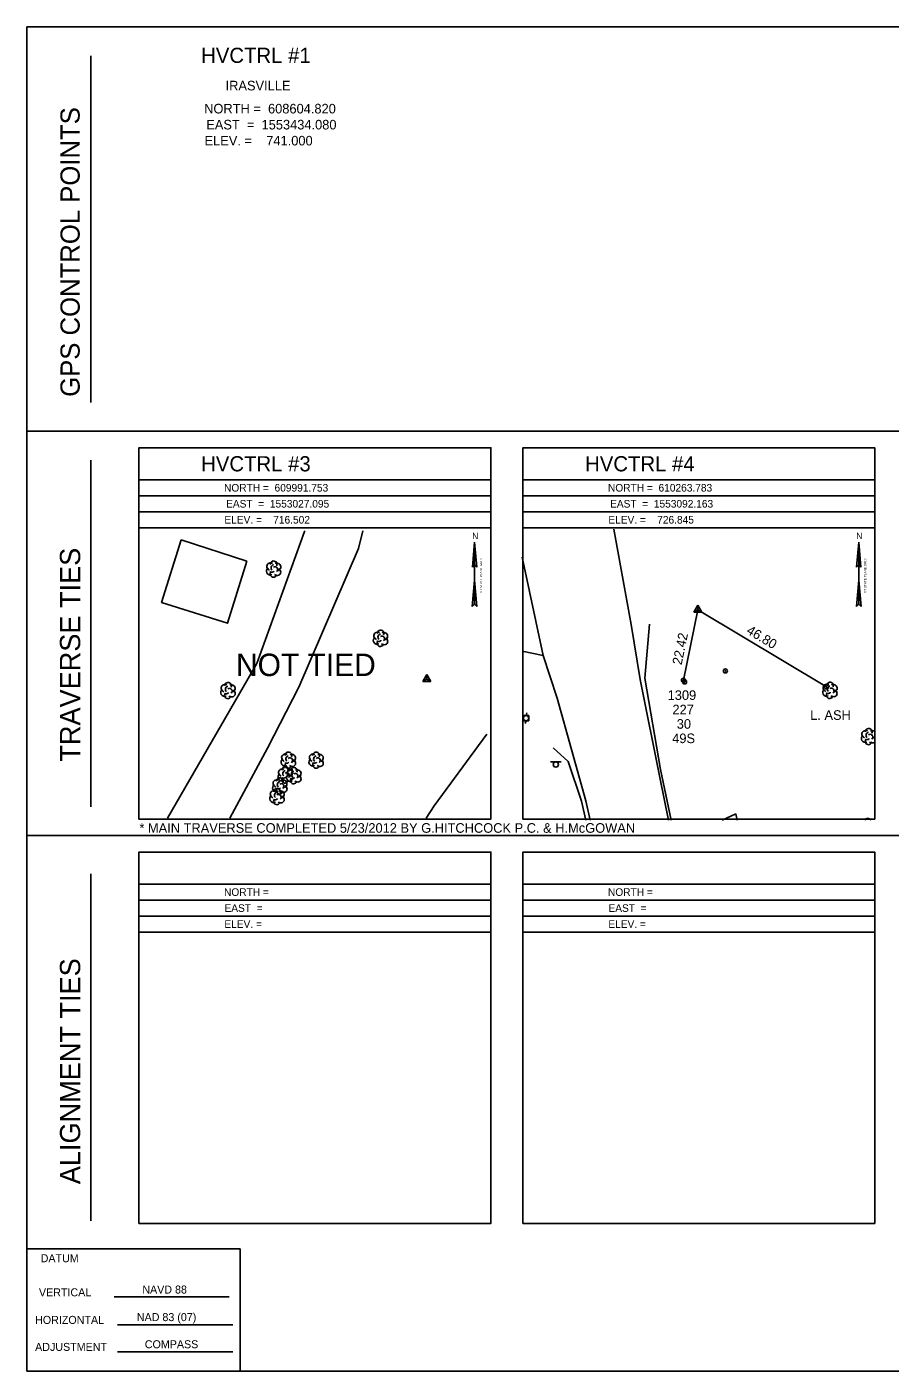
# Model space of a CAD drawing. Extents: x 1553683 to 1554323, y 609712 to 610132.
# Drawn here: x 1553683 to 1553952.8, y 609712.3 to 610132.3 of the extents above; entities that cross this region are included whole.
import ezdxf

# ---------------------------------------------------------------- set-up
doc = ezdxf.new("R2010")
doc.units = 0
for name, color, linetype in [('CBP', 7, 'Continuous'), ('CPSM', 7, 'Continuous'), ('Default', 7, 'Continuous'), ('L_C', 7, 'Continuous'), ('LAWA', 7, 'Continuous'), ('LAWE', 7, 'Continuous'), ('LBC', 7, 'Continuous'), ('LTD', 7, 'Continuous'), ('NBL1', 7, 'Continuous'), ('NBL2', 7, 'Continuous'), ('NNA_P', 7, 'Continuous'), ('PET', 7, 'Continuous'), ('PEU', 7, 'Continuous'), ('RGR', 7, 'Continuous'), ('SSGN', 7, 'Continuous'), ('U_C', 7, 'Continuous'), ('UP', 7, 'Continuous'), ('UPGW', 7, 'Continuous')]:
    doc.layers.add(name, color=color, linetype=linetype)

msp = doc.modelspace()

# ---------------------------------------------------------------- linework, layer by layer
at = {"layer": 'CBP'}
for centre, radius in [((1553888.16, 609928.2), 0.625), ((1553888.16, 609928.2), 0.0833), ((1553932.86, 609926.09), 0.625), ((1553932.86, 609926.09), 0.0833)]:
    msp.add_circle(centre, radius, dxfattribs=at)
at = {"layer": 'CPSM'}
for p, q in [((1553891.46, 609949.43), (1553892.71, 609951.6)), ((1553891.46, 609949.43), (1553892.71, 609950.15)), ((1553891.46, 609949.43), (1553893.96, 609949.43)), ((1553893.96, 609949.43), (1553892.71, 609951.6)), ((1553892.71, 609950.15), (1553892.71, 609951.6)), ((1553892.71, 609950.15), (1553892.71, 609950.15)), ((1553892.71, 609950.15), (1553893.96, 609949.43)), ((1553806.69, 609927.77), (1553807.94, 609929.94)), ((1553806.69, 609927.77), (1553807.94, 609928.49)), ((1553809.19, 609927.77), (1553807.94, 609929.94)), ((1553807.94, 609928.49), (1553807.94, 609929.94)), ((1553807.94, 609928.49), (1553807.94, 609928.49)), ((1553807.94, 609928.49), (1553809.19, 609927.77)), ((1553806.69, 609927.77), (1553809.19, 609927.77))]:
    msp.add_line(p, q, dxfattribs=at)
at = {"layer": 'Default'}
for p, q in [((1553888.16, 609928.2), (1553892.71, 609950.15)), ((1553892.71, 609950.15), (1553932.86, 609926.09))]:
    msp.add_line(p, q, dxfattribs=at)
at = {"layer": 'LAWA'}
for points in [[(1553904.54, 609886.5), (1553900.28, 609884.47)], [(1553904.54, 609886.5), (1553904.91, 609884.47)]]:
    msp.add_lwpolyline(points, dxfattribs=at)
at = {"layer": 'LAWE'}
msp.add_lwpolyline([(1553826.71, 609911.3), (1553810.31, 609889), (1553807.72, 609885.14)], dxfattribs=at)
at = {"layer": 'LBC'}
for points in [[(1553751.67, 609965.42), (1553745.63, 609946.01), (1553725.09, 609952.48), (1553731.24, 609972.07)], [(1553751.67, 609965.42), (1553731.24, 609972.07)]]:
    msp.add_lwpolyline(points, dxfattribs=at)
at = {"layer": 'LTD'}
for p, q in [((1553760.04, 609962.97), (1553760.04, 609962.97)), ((1553760.04, 609962.97), (1553760.04, 609962.97)), ((1553793.47, 609941.33), (1553793.47, 609941.33)), ((1553793.47, 609941.33), (1553793.47, 609941.33)), ((1553745.8, 609925), (1553745.8, 609925)), ((1553745.8, 609925), (1553745.8, 609925)), ((1553933.91, 609925.08), (1553933.91, 609925.08)), ((1553933.91, 609925.08), (1553933.91, 609925.08)), ((1553946.03, 609910.64), (1553946.03, 609910.64)), ((1553946.03, 609910.64), (1553946.03, 609910.64)), ((1553764.68, 609903.26), (1553764.68, 609903.26)), ((1553764.68, 609903.26), (1553764.68, 609903.26)), ((1553773.35, 609903.28), (1553773.35, 609903.28)), ((1553773.35, 609903.28), (1553773.35, 609903.28)), ((1553762, 609895.23), (1553762, 609895.23)), ((1553762, 609895.23), (1553762, 609895.23)), ((1553763.73, 609898.64), (1553763.73, 609898.64)), ((1553763.73, 609898.64), (1553763.73, 609898.64)), ((1553766.38, 609898.43), (1553766.38, 609898.43)), ((1553766.38, 609898.43), (1553766.38, 609898.43)), ((1553761.13, 609891.88), (1553761.13, 609891.88)), ((1553761.13, 609891.88), (1553761.13, 609891.88))]:
    msp.add_line(p, q, dxfattribs=at)
for centre, start, end in [((1553760.09, 609964.41), 335.5272, 180.9563), ((1553793.52, 609942.77), 335.5272, 180.9563), ((1553745.84, 609926.44), 335.5272, 180.9563), ((1553933.96, 609926.52), 335.5272, 180.9563), ((1553946.07, 609912.07), 335.5272, 180.9563), ((1553764.73, 609904.7), 335.5272, 180.9563), ((1553773.4, 609904.71), 335.5272, 180.9563), ((1553763.78, 609900.07), 335.5272, 180.9563), ((1553766.43, 609899.87), 335.5272, 180.9563), ((1553762.05, 609896.66), 335.5272, 180.9563), ((1553761.18, 609893.31), 335.5272, 180.9563), ((1553945.76, 609883.98), 27.7565, 152.2435)]:
    msp.add_arc(centre, 1.05, start, end, dxfattribs=at)
for centre, major_axis, ratio, start_param, end_param in [((1553758.96, 609962.26), (0.58, -1.04), 0.959034, 3.141593, 6.283185), ((1553759.25, 609963.64), (1.21, -0.51), 0.895232, 1.570796, 4.712389), ((1553759.58, 609962.22), (-0.625, -0.083), 0.423636, 0, 3.141593), ((1553759.83, 609963.43), (-0.208, -0.792), 0.645439, 3.141593, 6.283185), ((1553760.54, 609962.81), (-0.5, 0.667), 0.989748, 3.141593, 6.283185), ((1553761.04, 609962.14), (-1.09, 0.79), 0.841452, 1.570796, 4.712389), ((1553761.08, 609963.56), (-1.14, -0.48), 0.949671, 1.570796, 4.712389), ((1553760.04, 609961.47), (0.26, 1.06), 0.942809, 1.570796, 4.712389), ((1553792.39, 609940.62), (0.58, -1.04), 0.959034, 3.141593, 6.283185), ((1553792.68, 609942), (1.21, -0.51), 0.895232, 1.570796, 4.712389), ((1553793.26, 609941.79), (-0.208, -0.792), 0.645439, 3.141593, 6.283185), ((1553793.97, 609941.17), (-0.5, 0.667), 0.989748, 3.141593, 6.283185), ((1553794.47, 609940.5), (-1.09, 0.79), 0.841452, 1.570796, 4.712389), ((1553794.51, 609941.92), (-1.14, -0.48), 0.949671, 1.570796, 4.712389), ((1553793.47, 609939.83), (0.26, 1.06), 0.942809, 1.570796, 4.712389), ((1553793.01, 609940.58), (-0.625, -0.083), 0.423636, 0, 3.141593), ((1553744.71, 609924.3), (0.58, -1.04), 0.959034, 3.141593, 6.283185), ((1553745, 609925.67), (1.21, -0.51), 0.895232, 1.570796, 4.712389), ((1553745.34, 609924.25), (-0.625, -0.083), 0.423636, 0, 3.141593), ((1553745.59, 609925.46), (-0.208, -0.792), 0.645439, 3.141593, 6.283185), ((1553746.3, 609924.84), (-0.5, 0.667), 0.989748, 3.141593, 6.283185), ((1553746.8, 609924.17), (-1.09, 0.79), 0.841452, 1.570796, 4.712389), ((1553746.84, 609925.59), (-1.14, -0.48), 0.949671, 1.570796, 4.712389), ((1553932.83, 609924.38), (0.58, -1.04), 0.959034, 3.141593, 6.283185), ((1553933.12, 609925.75), (1.21, -0.51), 0.895232, 1.570796, 4.712389), ((1553933.45, 609924.33), (-0.625, -0.083), 0.423636, 0, 3.141593), ((1553933.7, 609925.54), (-0.208, -0.792), 0.645439, 3.141593, 6.283185), ((1553934.41, 609924.92), (-0.5, 0.667), 0.989748, 3.141593, 6.283185), ((1553934.91, 609924.25), (-1.09, 0.79), 0.841452, 1.570796, 4.712389), ((1553934.95, 609925.67), (-1.14, -0.48), 0.949671, 1.570796, 4.712389), ((1553745.8, 609923.5), (0.26, 1.06), 0.942809, 1.570796, 4.712389), ((1553933.91, 609923.58), (0.26, 1.06), 0.942809, 1.570796, 4.712389), ((1553945.24, 609911.3), (1.21, -0.51), 0.895232, 1.570796, 4.712389), ((1553945.82, 609911.09), (-0.208, -0.792), 0.645439, 3.141593, 6.283185), ((1553946.53, 609910.47), (-0.5, 0.667), 0.989748, 3.141593, 6.283185), ((1553947.07, 609911.22), (-1.14, -0.48), 0.949671, 3.816929, 4.712389), ((1553944.94, 609909.93), (0.58, -1.04), 0.959034, 3.141593, 6.283185), ((1553946.03, 609909.14), (0.26, 1.06), 0.942809, 1.570796, 4.712389), ((1553945.57, 609909.89), (-0.625, -0.083), 0.423636, 0, 3.141593), ((1553947.03, 609909.8), (-1.09, 0.79), 0.841452, 1.570796, 2.649237), ((1553947.07, 609911.22), (-1.14, -0.48), 0.949671, 1.570796, 1.701834), ((1553763.6, 609902.55), (0.58, -1.04), 0.959034, 3.141593, 6.283185), ((1553763.89, 609903.93), (1.21, -0.51), 0.895232, 1.570796, 4.712389), ((1553764.47, 609903.72), (-0.208, -0.792), 0.645439, 3.141593, 6.283185), ((1553765.18, 609903.1), (-0.5, 0.667), 0.989748, 3.141593, 6.283185), ((1553765.68, 609902.43), (-1.09, 0.79), 0.841452, 1.570796, 4.712389), ((1553765.72, 609903.85), (-1.14, -0.48), 0.949671, 1.570796, 4.712389), ((1553772.27, 609902.57), (0.58, -1.04), 0.959034, 3.141593, 6.283185), ((1553772.56, 609903.94), (1.21, -0.51), 0.895232, 1.570796, 4.712389), ((1553773.14, 609903.73), (-0.208, -0.792), 0.645439, 3.141593, 6.283185), ((1553773.85, 609903.11), (-0.5, 0.667), 0.989748, 3.141593, 6.283185), ((1553774.35, 609902.44), (-1.09, 0.79), 0.841452, 1.570796, 4.712389), ((1553774.39, 609903.86), (-1.14, -0.48), 0.949671, 1.570796, 4.712389), ((1553762.65, 609897.93), (0.58, -1.04), 0.959034, 3.141593, 6.283185), ((1553762.94, 609899.31), (1.21, -0.51), 0.895232, 1.570796, 4.712389), ((1553763.53, 609899.1), (-0.208, -0.792), 0.645439, 3.141593, 6.283185), ((1553764.68, 609901.76), (0.26, 1.06), 0.942809, 1.570796, 4.712389), ((1553764.22, 609902.51), (-0.625, -0.083), 0.423636, 0, 3.141593), ((1553764.23, 609898.47), (-0.5, 0.667), 0.989748, 3.141593, 6.283185), ((1553765.59, 609899.1), (1.21, -0.51), 0.895232, 1.570796, 4.712389), ((1553764.78, 609899.22), (-1.14, -0.48), 0.949671, 1.570796, 4.712389), ((1553766.18, 609898.89), (-0.208, -0.792), 0.645439, 3.141593, 6.283185), ((1553766.88, 609898.27), (-0.5, 0.667), 0.989748, 3.141593, 6.283185), ((1553767.43, 609899.02), (-1.14, -0.48), 0.949671, 1.570796, 4.712389), ((1553773.35, 609901.78), (0.26, 1.06), 0.942809, 1.570796, 4.712389), ((1553772.89, 609902.53), (-0.625, -0.083), 0.423636, 0, 3.141593), ((1553760.92, 609894.52), (0.58, -1.04), 0.959034, 3.141593, 6.283185), ((1553761.21, 609895.89), (1.21, -0.51), 0.895232, 1.570796, 4.712389), ((1553761.8, 609895.69), (-0.208, -0.792), 0.645439, 3.141593, 6.283185), ((1553762.5, 609895.06), (-0.5, 0.667), 0.989748, 3.141593, 6.283185), ((1553763, 609894.39), (-1.09, 0.79), 0.841452, 1.570796, 4.712389), ((1553763.74, 609897.14), (0.26, 1.06), 0.942809, 1.570796, 4.712389), ((1553763.05, 609895.81), (-1.14, -0.48), 0.949671, 1.570796, 4.712389), ((1553763.28, 609897.89), (-0.625, -0.083), 0.423636, 0, 3.141593), ((1553765.3, 609897.72), (0.58, -1.04), 0.959034, 3.141593, 6.283185), ((1553764.73, 609897.81), (-1.09, 0.79), 0.841452, 1.570796, 4.712389), ((1553766.38, 609896.93), (0.26, 1.06), 0.942809, 1.570796, 4.712389), ((1553765.93, 609897.68), (-0.625, -0.083), 0.423636, 0, 3.141593), ((1553767.38, 609897.6), (-1.09, 0.79), 0.841452, 1.570796, 4.712389), ((1553760.05, 609891.17), (0.58, -1.04), 0.959034, 3.141593, 6.283185), ((1553760.34, 609892.55), (1.21, -0.51), 0.895232, 1.570796, 4.712389), ((1553761.13, 609890.38), (0.26, 1.06), 0.942809, 1.570796, 4.712389), ((1553760.67, 609891.13), (-0.625, -0.083), 0.423636, 0, 3.141593), ((1553760.92, 609892.34), (-0.208, -0.792), 0.645439, 3.141593, 6.283185), ((1553762, 609893.73), (0.26, 1.06), 0.942809, 1.570796, 4.712389), ((1553761.55, 609894.48), (-0.625, -0.083), 0.423636, 0, 3.141593), ((1553761.63, 609891.71), (-0.5, 0.667), 0.989748, 3.141593, 6.283185), ((1553762.13, 609891.05), (-1.09, 0.79), 0.841452, 1.570796, 4.712389), ((1553762.17, 609892.46), (-1.14, -0.48), 0.949671, 1.570796, 4.712389)]:
    msp.add_ellipse(centre, major_axis=major_axis, ratio=ratio, start_param=start_param, end_param=end_param, dxfattribs=at)
at = {"layer": 'NBL1'}
msp.add_lwpolyline([(1553682.98, 609712.33), (1554322.98, 609712.33), (1554322.98, 610132.33), (1553682.98, 610132.33)], close=True, dxfattribs=at)
at = {"layer": 'NBL2'}
for p, q in [((1553702.98, 610014.99), (1553702.98, 610123.33)), ((1553682.98, 610005.99), (1554322.98, 610005.99)), ((1553702.98, 609888.66), (1553702.98, 609996.99)), ((1553827.98, 609990.83), (1553717.98, 609990.83)), ((1553947.98, 609990.83), (1553837.98, 609990.83)), ((1553827.98, 609985.83), (1553717.98, 609985.83)), ((1553947.98, 609985.83), (1553837.98, 609985.83)), ((1553827.98, 609980.83), (1553717.98, 609980.83)), ((1553947.98, 609980.83), (1553837.98, 609980.83)), ((1553827.98, 609975.83), (1553717.98, 609975.83)), ((1553947.98, 609975.83), (1553837.98, 609975.83)), ((1553682.98, 609879.66), (1554322.98, 609879.66)), ((1553702.98, 609759.33), (1553702.98, 609867.66)), ((1553827.98, 609864.49), (1553717.98, 609864.49)), ((1553947.98, 609864.49), (1553837.98, 609864.49)), ((1553827.98, 609859.49), (1553717.98, 609859.49)), ((1553947.98, 609859.49), (1553837.98, 609859.49)), ((1553827.98, 609854.49), (1553717.98, 609854.49)), ((1553947.98, 609854.49), (1553837.98, 609854.49)), ((1553827.98, 609849.49), (1553717.98, 609849.49)), ((1553947.98, 609849.49), (1553837.98, 609849.49)), ((1553749.64, 609750.58), (1553682.98, 609750.58)), ((1553749.64, 609750.58), (1553749.64, 609712.33)), ((1553749.64, 609750.58), (1553749.64, 609712.33)), ((1553710.22, 609735.56), (1553746.22, 609735.52)), ((1553711.33, 609726.78), (1553747.33, 609726.78)), ((1553711.33, 609718.35), (1553747.33, 609718.31))]:
    msp.add_line(p, q, dxfattribs=at)
for points in [[(1553717.98, 609884.83), (1553827.98, 609884.83), (1553827.98, 610000.83), (1553717.98, 610000.83)], [(1553837.98, 609884.83), (1553947.98, 609884.83), (1553947.98, 610000.83), (1553837.98, 610000.83)], [(1553717.98, 609758.49), (1553827.98, 609758.49), (1553827.98, 609874.49), (1553717.98, 609874.49)], [(1553837.98, 609758.49), (1553947.98, 609758.49), (1553947.98, 609874.49), (1553837.98, 609874.49)]]:
    msp.add_lwpolyline(points, close=True, dxfattribs=at)
at = {"layer": 'NNA_P'}
for p, q in [((1553822.22, 609963.5), (1553822.91, 609971.29)), ((1553822.91, 609951.92), (1553822.91, 609971.29)), ((1553823.6, 609963.5), (1553822.91, 609971.29)), ((1553942.27, 609963.5), (1553942.96, 609971.29)), ((1553942.97, 609951.92), (1553942.96, 609971.29)), ((1553943.66, 609963.5), (1553942.96, 609971.29)), ((1553822.22, 609963.5), (1553822.91, 609964.27)), ((1553823.61, 609963.5), (1553822.91, 609964.27)), ((1553942.27, 609963.5), (1553942.96, 609964.27)), ((1553943.66, 609963.5), (1553942.97, 609964.27)), ((1553822.91, 609959.44), (1553822.19, 609951.28)), ((1553822.91, 609959.44), (1553823.63, 609951.28)), ((1553942.97, 609959.44), (1553942.25, 609951.28)), ((1553942.97, 609959.44), (1553943.69, 609951.28)), ((1553822.91, 609951.92), (1553822.19, 609951.28)), ((1553822.91, 609951.92), (1553823.63, 609951.28)), ((1553942.97, 609951.92), (1553942.25, 609951.28)), ((1553942.97, 609951.92), (1553943.69, 609951.28))]:
    msp.add_line(p, q, dxfattribs=at)
at = {"layer": 'PET'}
for points in [[(1553866.42, 609975.34), (1553871.8, 609945.63), (1553874.64, 609928.45), (1553880.89, 609897.3), (1553883.54, 609884.47)], [(1553837.8, 609966.65), (1553844.38, 609935.9), (1553848.71, 609922.59), (1553857.67, 609890.53), (1553858.99, 609884.47)], [(1553837.8, 609937.23), (1553844.38, 609935.9)]]:
    msp.add_lwpolyline(points, dxfattribs=at)
at = {"layer": 'PEU'}
for points in [[(1553769.83, 609974.89), (1553769.77, 609974.64), (1553754.81, 609933.37), (1553743.59, 609913.95), (1553726.89, 609885.14)], [(1553788.02, 609974.89), (1553786.66, 609969.34), (1553767.98, 609925.98), (1553758.18, 609906.97), (1553746.41, 609885.14)]]:
    msp.add_lwpolyline(points, dxfattribs=at)
at = {"layer": 'RGR'}
for points in [[(1553877.57, 609945.66), (1553876.13, 609928.88), (1553880.98, 609900.27), (1553884.36, 609884.47)], [(1553847.49, 609907.04), (1553852.16, 609902.79), (1553856.28, 609890.38), (1553857.69, 609884.47)]]:
    msp.add_lwpolyline(points, dxfattribs=at)
at = {"layer": 'SSGN'}
for p, q in [((1553846.65, 609902.7), (1553849.98, 609902.7)), ((1553848.3, 609901.87), (1553848.3, 609901.87))]:
    msp.add_line(p, q, dxfattribs=at)
msp.add_circle((1553848.3, 609901.87), 0.833, dxfattribs=at)
at = {"layer": 'UP'}
for p, q in [((1553838.16, 609915.49), (1553838.16, 609917.16)), ((1553838.16, 609917.16), (1553839.83, 609917.16)), ((1553839.25, 609917.99), (1553839, 609917.16)), ((1553839, 609916.33), (1553839, 609916.33)), ((1553839.83, 609917.16), (1553839.83, 609915.49)), ((1553839.83, 609915.49), (1553838.16, 609915.49)), ((1553838.75, 609914.66), (1553839, 609915.49))]:
    msp.add_line(p, q, dxfattribs=at)
msp.add_circle((1553839, 609916.33), 0.833, dxfattribs=at)
at = {"layer": 'UPGW'}
for centre, radius in [((1553888.55, 609927.66), 0.625), ((1553901.28, 609931.09), 0.625), ((1553901.28, 609931.09), 0.0833), ((1553888.55, 609927.66), 0.0833)]:
    msp.add_circle(centre, radius, dxfattribs=at)

# ---------------------------------------------------------------- texts
at = {"layer": 'Default'}
for s, rotation, p in [('22.42', 78.3095, (1553887.59, 609932.82)), ('46.80', 329.0655, (1553907.61, 609942.97))]:
    msp.add_text(s, height=3, rotation=rotation, dxfattribs=at).set_placement(p)
for s, height, p in [('NOT TIED', 7, (1553748.33, 609929.5)), ('* MAIN TRAVERSE COMPLETED 5/23/2012 BY G.HITCHCOCK P.C. & H.McGOWAN', 3, (1553718.14, 609880.53))]:
    msp.add_text(s, height=height, dxfattribs=at).set_placement(p)
at = {"layer": 'L_C'}
msp.add_text('L. ASH', height=3, dxfattribs=at).set_placement((1553927.78, 609915.81))
at = {"layer": 'NBL2'}
for s, height, p in [('     HVCTRL #1     ', 4.75, (1553728.62, 610121.06)), ('      IRASVILLE     ', 3, (1553738.39, 610112.48)), ('NORTH =  608604.820 ', 3, (1553738.39, 610105.28)), ('EAST  =  1553434.080', 3, (1553739.04, 610100.28)), ('ELEV. =    741.000  ', 3, (1553738.5, 610095.28)), ('     HVCTRL #3     ', 4.75, (1553728.62, 609993.45)), ('     HVCTRL #4     ', 4.75, (1553848.62, 609993.45)), ('NORTH =  609991.753 ', 2.375, (1553744.59, 609987.14)), ('NORTH =  610263.783 ', 2.375, (1553864.59, 609987.14)), ('EAST  =  1553027.095', 2.375, (1553745.24, 609982.14)), ('EAST  =  1553092.163', 2.375, (1553865.24, 609982.14)), ('ELEV. =    716.502  ', 2.375, (1553744.7, 609977.14)), ('ELEV. =    726.845  ', 2.375, (1553864.7, 609977.14)), ('NORTH =             ', 2.375, (1553744.59, 609860.81)), ('NORTH =             ', 2.375, (1553864.59, 609860.81)), ('EAST  =             ', 2.375, (1553744.74, 609855.81)), ('EAST  =             ', 2.375, (1553864.74, 609855.81)), ('ELEV. =             ', 2.375, (1553744.7, 609850.81)), ('ELEV. =             ', 2.375, (1553864.7, 609850.81)), ('DATUM', 2.5, (1553687.29, 609746.34)), ('  NAVD 88 ', 2.5, (1553717.2, 609736.57)), ('HORIZONTAL', 2.5, (1553685.55, 609727.08)), ('NAD 83 (07)', 2.5, (1553717.35, 609727.95)), ('ADJUSTMENT', 2.5, (1553685.55, 609718.64)), ('  COMPASS ', 2.5, (1553717.97, 609719.47))]:
    msp.add_text(s, height=height, dxfattribs=at).set_placement(p)
for s, height, rotation, p in [('GPS CONTROL POINTS', 6, 90, (1553699.48, 610016.74)), ('TRAVERSE TIES', 6.3332, 90, (1553699.64, 609902.76)), ('ALIGNMENT TIES', 6.3332, 90, (1553699.64, 609770.73)), ('VERTICAL', 2.5, 0.1439, (1553686.75, 609735.67))]:
    msp.add_text(s, height=height, rotation=rotation, dxfattribs=at).set_placement(p)
at = {"layer": 'NNA_P'}
for p in [(1553822.15, 609972.3), (1553942.2, 609972.3)]:
    msp.add_text('N', height=1.97, dxfattribs=at).set_placement(p)
for p in [(1553825.26, 609955.48), (1553945.32, 609955.48)]:
    msp.add_text('VT STATE PLANE GRID', height=0.7, rotation=90.0204, dxfattribs=at).set_placement(p)
at = {"layer": 'U_C'}
for s, p in [('1309', (1553883.23, 609922.04)), ('227', (1553884.73, 609917.54)), ('30', (1553886.08, 609913.04)), ('49S', (1553884.66, 609908.54))]:
    msp.add_text(s, height=3, dxfattribs=at).set_placement(p)

doc.saveas('drawing.dxf')
